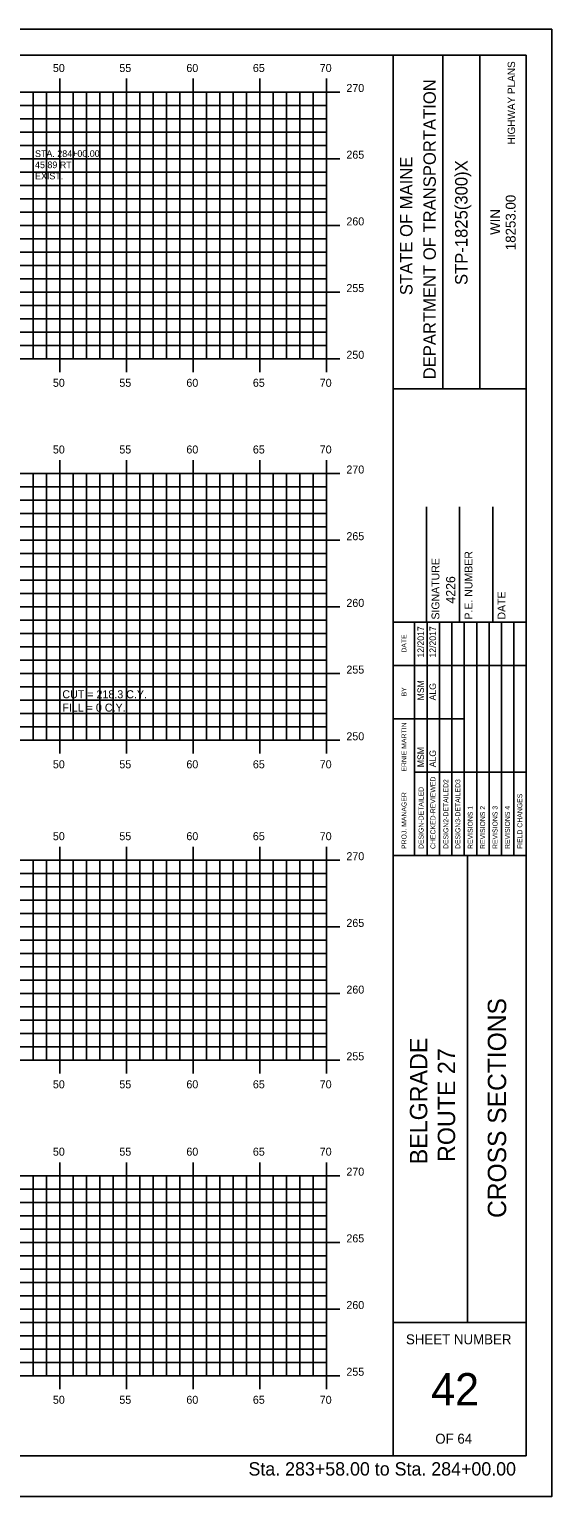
# Model space of a CAD drawing. Extents: x 856235 to 856405, y 366268 to 366378.
# Drawn here: x 856365.5 to 856404.7, y 366268.2 to 366378.2 of the extents above; entities that cross this region are included whole.
import ezdxf

# ---------------------------------------------------------------- set-up
doc = ezdxf.new("R2010")
doc.units = 0
for name, color, linetype in [('ANNOTATION', 7, 'Continuous'), ('BORDER', 7, 'Continuous'), ('D_Text_Monospaced', 7, 'Continuous'), ('H_V ANNOTATION', 7, 'Continuous'), ('HIGHWAY_TITLE', 7, 'Continuous'), ('MAJOR', 7, 'Continuous'), ('MINOR', 7, 'Continuous'), ('PLOT BOUNDARY', 7, 'Continuous')]:
    doc.layers.add(name, color=color, linetype=linetype)

msp = doc.modelspace()

# ---------------------------------------------------------------- linework, layer by layer
at = {"layer": 'BORDER'}
for p, q in [((856402.78, 366376.24), (856242.78, 366376.24)), ((856392.78, 366271.24), (856392.78, 366376.24)), ((856396.51, 366351.23), (856396.51, 366376.23)), ((856399.3, 366351.23), (856399.3, 366376.23)), ((856402.78, 366271.24), (856402.78, 366376.24)), ((856392.78, 366351.23), (856402.78, 366351.23)), ((856395.28, 366333.74), (856395.28, 366342.39)), ((856397.78, 366333.74), (856397.78, 366342.39)), ((856400.28, 366333.74), (856400.28, 366342.39)), ((856392.78, 366333.74), (856402.78, 366333.74)), ((856392.78, 366316.24), (856402.78, 366316.24)), ((856398.37, 366281.24), (856398.37, 366316.24)), ((856392.78, 366281.24), (856402.78, 366281.24)), ((856242.78, 366271.24), (856402.78, 366271.24))]:
    msp.add_line(p, q, dxfattribs=at)
for points in [[(856394.4, 366330.49), (856394.4, 366333.74)], [(856394.4, 366316.24), (856394.4, 366333.03)], [(856395.33, 366316.24), (856395.33, 366333.74)], [(856396.26, 366333.74), (856396.26, 366316.24)], [(856397.19, 366316.24), (856397.19, 366333.74)], [(856398.12, 366316.24), (856398.12, 366333.74)], [(856399.06, 366316.24), (856399.06, 366333.74)], [(856399.99, 366316.24), (856399.99, 366333.74)], [(856400.92, 366316.24), (856400.92, 366333.74)], [(856401.85, 366316.24), (856401.85, 366333.74)], [(856392.78, 366330.49), (856402.78, 366330.49)], [(856392.78, 366326.49), (856394.4, 366326.49)], [(856394.4, 366326.49), (856398.12, 366326.49)], [(856394.4, 366322.49), (856402.78, 366322.49)]]:
    msp.add_lwpolyline(points, dxfattribs=at)
at = {"layer": 'MAJOR'}
for p, q in [((856367.78, 366374.48), (856367.78, 366373.48)), ((856372.78, 366374.48), (856372.78, 366373.48)), ((856377.78, 366374.48), (856377.78, 366373.48)), ((856382.78, 366374.48), (856382.78, 366373.48)), ((856387.78, 366374.48), (856387.78, 366373.48)), ((856247.78, 366373.48), (856387.78, 366373.48)), ((856247.78, 366373.48), (856387.78, 366373.48)), ((856367.78, 366353.48), (856367.78, 366373.48)), ((856372.78, 366353.48), (856372.78, 366373.48)), ((856377.78, 366353.48), (856377.78, 366373.48)), ((856382.78, 366353.48), (856382.78, 366373.48)), ((856388.78, 366373.48), (856386.78, 366373.48)), ((856387.78, 366353.48), (856387.78, 366373.48)), ((856387.78, 366353.48), (856387.78, 366373.48)), ((856247.78, 366368.48), (856387.78, 366368.48)), ((856388.78, 366368.48), (856386.78, 366368.48)), ((856247.78, 366363.48), (856387.78, 366363.48)), ((856388.78, 366363.48), (856386.78, 366363.48)), ((856247.78, 366358.48), (856387.78, 366358.48)), ((856388.78, 366358.48), (856386.78, 366358.48)), ((856247.78, 366353.48), (856387.78, 366353.48)), ((856247.78, 366353.48), (856387.78, 366353.48)), ((856367.78, 366352.48), (856367.78, 366353.48)), ((856372.78, 366352.48), (856372.78, 366353.48)), ((856377.78, 366352.48), (856377.78, 366353.48)), ((856382.78, 366352.48), (856382.78, 366353.48)), ((856388.78, 366353.48), (856386.78, 366353.48)), ((856387.78, 366352.48), (856387.78, 366353.48)), ((856367.78, 366345.89), (856367.78, 366344.88)), ((856372.78, 366345.89), (856372.78, 366344.88)), ((856377.78, 366345.89), (856377.78, 366344.88)), ((856382.78, 366345.89), (856382.78, 366344.88)), ((856387.78, 366345.89), (856387.78, 366344.88)), ((856247.78, 366344.88), (856387.78, 366344.88)), ((856247.78, 366344.88), (856387.78, 366344.88)), ((856367.78, 366324.88), (856367.78, 366344.88)), ((856372.78, 366324.88), (856372.78, 366344.88)), ((856377.78, 366324.88), (856377.78, 366344.88)), ((856382.78, 366324.88), (856382.78, 366344.88)), ((856388.78, 366344.88), (856386.78, 366344.88)), ((856387.78, 366324.88), (856387.78, 366344.88)), ((856387.78, 366324.88), (856387.78, 366344.88)), ((856247.78, 366339.88), (856387.78, 366339.88)), ((856388.78, 366339.88), (856386.78, 366339.88)), ((856247.78, 366334.88), (856387.78, 366334.88)), ((856388.78, 366334.88), (856386.78, 366334.88)), ((856247.78, 366329.88), (856387.78, 366329.88)), ((856388.78, 366329.88), (856386.78, 366329.88)), ((856247.78, 366324.88), (856387.78, 366324.88)), ((856247.78, 366324.88), (856387.78, 366324.88)), ((856367.78, 366323.88), (856367.78, 366324.88)), ((856372.78, 366323.88), (856372.78, 366324.88)), ((856377.78, 366323.88), (856377.78, 366324.88)), ((856382.78, 366323.88), (856382.78, 366324.88)), ((856388.78, 366324.88), (856386.78, 366324.88)), ((856387.78, 366323.88), (856387.78, 366324.88)), ((856367.78, 366316.89), (856367.78, 366315.89)), ((856372.78, 366316.89), (856372.78, 366315.89)), ((856377.78, 366316.89), (856377.78, 366315.89)), ((856382.78, 366316.89), (856382.78, 366315.89)), ((856387.78, 366316.89), (856387.78, 366315.89)), ((856247.78, 366315.89), (856387.78, 366315.89)), ((856247.78, 366315.89), (856387.78, 366315.89)), ((856367.78, 366300.89), (856367.78, 366315.89)), ((856372.78, 366300.89), (856372.78, 366315.89)), ((856377.78, 366300.89), (856377.78, 366315.89)), ((856382.78, 366300.89), (856382.78, 366315.89)), ((856388.78, 366315.89), (856386.78, 366315.89)), ((856387.78, 366300.89), (856387.78, 366315.89)), ((856387.78, 366300.89), (856387.78, 366315.89)), ((856247.78, 366310.89), (856387.78, 366310.89)), ((856388.78, 366310.89), (856386.78, 366310.89)), ((856247.78, 366305.89), (856387.78, 366305.89)), ((856388.78, 366305.89), (856386.78, 366305.89)), ((856247.78, 366300.89), (856387.78, 366300.89)), ((856247.78, 366300.89), (856387.78, 366300.89)), ((856367.78, 366299.89), (856367.78, 366300.89)), ((856372.78, 366299.89), (856372.78, 366300.89)), ((856377.78, 366299.89), (856377.78, 366300.89)), ((856382.78, 366299.89), (856382.78, 366300.89)), ((856388.78, 366300.89), (856386.78, 366300.89)), ((856387.78, 366299.89), (856387.78, 366300.89)), ((856367.78, 366293.24), (856367.78, 366292.24)), ((856372.78, 366293.24), (856372.78, 366292.24)), ((856377.78, 366293.24), (856377.78, 366292.24)), ((856382.78, 366293.24), (856382.78, 366292.24)), ((856387.78, 366293.24), (856387.78, 366292.24)), ((856247.78, 366292.24), (856387.78, 366292.24)), ((856247.78, 366292.24), (856387.78, 366292.24)), ((856367.78, 366277.24), (856367.78, 366292.24)), ((856372.78, 366277.24), (856372.78, 366292.24)), ((856377.78, 366277.24), (856377.78, 366292.24)), ((856382.78, 366277.24), (856382.78, 366292.24)), ((856388.78, 366292.24), (856386.78, 366292.24)), ((856387.78, 366277.24), (856387.78, 366292.24)), ((856387.78, 366277.24), (856387.78, 366292.24)), ((856247.78, 366287.24), (856387.78, 366287.24)), ((856388.78, 366287.24), (856386.78, 366287.24)), ((856247.78, 366282.24), (856387.78, 366282.24)), ((856388.78, 366282.24), (856386.78, 366282.24)), ((856247.78, 366277.24), (856387.78, 366277.24)), ((856247.78, 366277.24), (856387.78, 366277.24)), ((856367.78, 366276.23), (856367.78, 366277.24)), ((856372.78, 366276.23), (856372.78, 366277.24)), ((856377.78, 366276.23), (856377.78, 366277.24)), ((856382.78, 366276.23), (856382.78, 366277.24)), ((856388.78, 366277.24), (856386.78, 366277.24)), ((856387.78, 366276.23), (856387.78, 366277.24))]:
    msp.add_line(p, q, dxfattribs=at)
at = {"layer": 'MINOR'}
for p, q in [((856365.78, 366353.48), (856365.78, 366373.48)), ((856366.78, 366353.48), (856366.78, 366373.48)), ((856368.78, 366353.48), (856368.78, 366373.48)), ((856369.78, 366353.48), (856369.78, 366373.48)), ((856370.78, 366353.48), (856370.78, 366373.48)), ((856371.78, 366353.48), (856371.78, 366373.48)), ((856373.78, 366353.48), (856373.78, 366373.48)), ((856374.78, 366353.48), (856374.78, 366373.48)), ((856375.78, 366353.48), (856375.78, 366373.48)), ((856376.78, 366353.48), (856376.78, 366373.48)), ((856378.78, 366353.48), (856378.78, 366373.48)), ((856379.78, 366353.48), (856379.78, 366373.48)), ((856380.78, 366353.48), (856380.78, 366373.48)), ((856381.78, 366353.48), (856381.78, 366373.48)), ((856383.78, 366353.48), (856383.78, 366373.48)), ((856384.78, 366353.48), (856384.78, 366373.48)), ((856385.78, 366353.48), (856385.78, 366373.48)), ((856386.78, 366353.48), (856386.78, 366373.48)), ((856247.78, 366372.48), (856387.78, 366372.48)), ((856387.78, 366372.48), (856386.78, 366372.48)), ((856247.78, 366371.48), (856387.78, 366371.48)), ((856247.78, 366370.48), (856387.78, 366370.48)), ((856387.78, 366371.48), (856386.78, 366371.48)), ((856387.78, 366370.48), (856386.78, 366370.48)), ((856247.78, 366369.48), (856387.78, 366369.48)), ((856387.78, 366369.48), (856386.78, 366369.48)), ((856247.78, 366367.48), (856387.78, 366367.48)), ((856387.78, 366367.48), (856386.78, 366367.48)), ((856247.78, 366366.48), (856387.78, 366366.48)), ((856387.78, 366366.48), (856386.78, 366366.48)), ((856247.78, 366365.48), (856387.78, 366365.48)), ((856387.78, 366365.48), (856386.78, 366365.48)), ((856247.78, 366364.48), (856387.78, 366364.48)), ((856387.78, 366364.48), (856386.78, 366364.48)), ((856247.78, 366362.48), (856387.78, 366362.48)), ((856387.78, 366362.48), (856386.78, 366362.48)), ((856247.78, 366361.48), (856387.78, 366361.48)), ((856387.78, 366361.48), (856386.78, 366361.48)), ((856247.78, 366360.48), (856387.78, 366360.48)), ((856247.78, 366359.48), (856387.78, 366359.48)), ((856387.78, 366360.48), (856386.78, 366360.48)), ((856387.78, 366359.48), (856386.78, 366359.48)), ((856247.78, 366357.48), (856387.78, 366357.48)), ((856387.78, 366357.48), (856386.78, 366357.48)), ((856247.78, 366356.48), (856387.78, 366356.48)), ((856387.78, 366356.48), (856386.78, 366356.48)), ((856247.78, 366355.48), (856387.78, 366355.48)), ((856387.78, 366355.48), (856386.78, 366355.48)), ((856247.78, 366354.48), (856387.78, 366354.48)), ((856387.78, 366354.48), (856386.78, 366354.48)), ((856365.78, 366324.88), (856365.78, 366344.88)), ((856366.78, 366324.88), (856366.78, 366344.88)), ((856368.78, 366324.88), (856368.78, 366344.88)), ((856369.78, 366324.88), (856369.78, 366344.88)), ((856370.78, 366324.88), (856370.78, 366344.88)), ((856371.78, 366324.88), (856371.78, 366344.88)), ((856373.78, 366324.88), (856373.78, 366344.88)), ((856374.78, 366324.88), (856374.78, 366344.88)), ((856375.78, 366324.88), (856375.78, 366344.88)), ((856376.78, 366324.88), (856376.78, 366344.88)), ((856378.78, 366324.88), (856378.78, 366344.88)), ((856379.78, 366324.88), (856379.78, 366344.88)), ((856380.78, 366324.88), (856380.78, 366344.88)), ((856381.78, 366324.88), (856381.78, 366344.88)), ((856383.78, 366324.88), (856383.78, 366344.88)), ((856384.78, 366324.88), (856384.78, 366344.88)), ((856385.78, 366324.88), (856385.78, 366344.88)), ((856386.78, 366324.88), (856386.78, 366344.88)), ((856247.78, 366343.88), (856387.78, 366343.88)), ((856387.78, 366343.88), (856386.78, 366343.88)), ((856247.78, 366342.88), (856387.78, 366342.88)), ((856247.78, 366341.88), (856387.78, 366341.88)), ((856387.78, 366342.88), (856386.78, 366342.88)), ((856387.78, 366341.88), (856386.78, 366341.88)), ((856247.78, 366340.88), (856387.78, 366340.88)), ((856387.78, 366340.88), (856386.78, 366340.88)), ((856247.78, 366338.88), (856387.78, 366338.88)), ((856387.78, 366338.88), (856386.78, 366338.88)), ((856247.78, 366337.88), (856387.78, 366337.88)), ((856387.78, 366337.88), (856386.78, 366337.88)), ((856247.78, 366336.88), (856387.78, 366336.88)), ((856387.78, 366336.88), (856386.78, 366336.88)), ((856247.78, 366335.88), (856387.78, 366335.88)), ((856387.78, 366335.88), (856386.78, 366335.88)), ((856247.78, 366333.88), (856387.78, 366333.88)), ((856387.78, 366333.88), (856386.78, 366333.88)), ((856247.78, 366332.88), (856387.78, 366332.88)), ((856387.78, 366332.88), (856386.78, 366332.88)), ((856247.78, 366331.88), (856387.78, 366331.88)), ((856247.78, 366330.88), (856387.78, 366330.88)), ((856387.78, 366331.88), (856386.78, 366331.88)), ((856387.78, 366330.88), (856386.78, 366330.88)), ((856247.78, 366328.88), (856387.78, 366328.88)), ((856387.78, 366328.88), (856386.78, 366328.88)), ((856247.78, 366327.88), (856387.78, 366327.88)), ((856387.78, 366327.88), (856386.78, 366327.88)), ((856247.78, 366326.88), (856387.78, 366326.88)), ((856387.78, 366326.88), (856386.78, 366326.88)), ((856247.78, 366325.88), (856387.78, 366325.88)), ((856387.78, 366325.88), (856386.78, 366325.88)), ((856365.78, 366300.89), (856365.78, 366315.89)), ((856366.78, 366300.89), (856366.78, 366315.89)), ((856368.78, 366300.89), (856368.78, 366315.89)), ((856369.78, 366300.89), (856369.78, 366315.89)), ((856370.78, 366300.89), (856370.78, 366315.89)), ((856371.78, 366300.89), (856371.78, 366315.89)), ((856373.78, 366300.89), (856373.78, 366315.89)), ((856374.78, 366300.89), (856374.78, 366315.89)), ((856375.78, 366300.89), (856375.78, 366315.89)), ((856376.78, 366300.89), (856376.78, 366315.89)), ((856378.78, 366300.89), (856378.78, 366315.89)), ((856379.78, 366300.89), (856379.78, 366315.89)), ((856380.78, 366300.89), (856380.78, 366315.89)), ((856381.78, 366300.89), (856381.78, 366315.89)), ((856383.78, 366300.89), (856383.78, 366315.89)), ((856384.78, 366300.89), (856384.78, 366315.89)), ((856385.78, 366300.89), (856385.78, 366315.89)), ((856386.78, 366300.89), (856386.78, 366315.89)), ((856247.78, 366314.89), (856387.78, 366314.89)), ((856387.78, 366314.89), (856386.78, 366314.89)), ((856247.78, 366313.89), (856387.78, 366313.89)), ((856387.78, 366313.89), (856386.78, 366313.89)), ((856247.78, 366312.89), (856387.78, 366312.89)), ((856387.78, 366312.89), (856386.78, 366312.89)), ((856247.78, 366311.89), (856387.78, 366311.89)), ((856387.78, 366311.89), (856386.78, 366311.89)), ((856247.78, 366309.89), (856387.78, 366309.89)), ((856247.78, 366308.89), (856387.78, 366308.89)), ((856387.78, 366309.89), (856386.78, 366309.89)), ((856387.78, 366308.89), (856386.78, 366308.89)), ((856247.78, 366307.89), (856387.78, 366307.89)), ((856387.78, 366307.89), (856386.78, 366307.89)), ((856247.78, 366306.89), (856387.78, 366306.89)), ((856387.78, 366306.89), (856386.78, 366306.89)), ((856247.78, 366304.89), (856387.78, 366304.89)), ((856387.78, 366304.89), (856386.78, 366304.89)), ((856247.78, 366303.89), (856387.78, 366303.89)), ((856387.78, 366303.89), (856386.78, 366303.89)), ((856247.78, 366302.89), (856387.78, 366302.89)), ((856387.78, 366302.89), (856386.78, 366302.89)), ((856247.78, 366301.89), (856387.78, 366301.89)), ((856387.78, 366301.89), (856386.78, 366301.89)), ((856247.78, 366291.24), (856387.78, 366291.24)), ((856365.78, 366277.24), (856365.78, 366292.24)), ((856366.78, 366277.24), (856366.78, 366292.24)), ((856368.78, 366277.24), (856368.78, 366292.24)), ((856369.78, 366277.24), (856369.78, 366292.24)), ((856370.78, 366277.24), (856370.78, 366292.24)), ((856371.78, 366277.24), (856371.78, 366292.24)), ((856373.78, 366277.24), (856373.78, 366292.24)), ((856374.78, 366277.24), (856374.78, 366292.24)), ((856375.78, 366277.24), (856375.78, 366292.24)), ((856376.78, 366277.24), (856376.78, 366292.24)), ((856378.78, 366277.24), (856378.78, 366292.24)), ((856379.78, 366277.24), (856379.78, 366292.24)), ((856380.78, 366277.24), (856380.78, 366292.24)), ((856381.78, 366277.24), (856381.78, 366292.24)), ((856383.78, 366277.24), (856383.78, 366292.24)), ((856384.78, 366277.24), (856384.78, 366292.24)), ((856385.78, 366277.24), (856385.78, 366292.24)), ((856386.78, 366277.24), (856386.78, 366292.24)), ((856387.78, 366291.24), (856386.78, 366291.24)), ((856247.78, 366290.24), (856387.78, 366290.24)), ((856387.78, 366290.24), (856386.78, 366290.24)), ((856247.78, 366289.24), (856387.78, 366289.24)), ((856387.78, 366289.24), (856386.78, 366289.24)), ((856247.78, 366288.24), (856387.78, 366288.24)), ((856387.78, 366288.24), (856386.78, 366288.24)), ((856247.78, 366286.24), (856387.78, 366286.24)), ((856387.78, 366286.24), (856386.78, 366286.24)), ((856247.78, 366285.24), (856387.78, 366285.24)), ((856387.78, 366285.24), (856386.78, 366285.24)), ((856247.78, 366284.24), (856387.78, 366284.24)), ((856387.78, 366284.24), (856386.78, 366284.24)), ((856247.78, 366283.24), (856387.78, 366283.24)), ((856387.78, 366283.24), (856386.78, 366283.24)), ((856247.78, 366281.24), (856387.78, 366281.24)), ((856247.78, 366280.24), (856387.78, 366280.24)), ((856387.78, 366281.24), (856386.78, 366281.24)), ((856387.78, 366280.24), (856386.78, 366280.24)), ((856247.78, 366279.24), (856387.78, 366279.24)), ((856387.78, 366279.24), (856386.78, 366279.24)), ((856247.78, 366278.24), (856387.78, 366278.24)), ((856387.78, 366278.24), (856386.78, 366278.24))]:
    msp.add_line(p, q, dxfattribs=at)
at = {"layer": 'PLOT BOUNDARY'}
msp.add_lwpolyline([(856234.69, 366268.18), (856404.69, 366268.18), (856404.69, 366378.18), (856234.69, 366378.18)], close=True, dxfattribs=at)

# ---------------------------------------------------------------- texts
at = {"layer": 'ANNOTATION'}
msp.add_text('4226', height=0.69, rotation=90, dxfattribs=at).set_placement((856397.45, 366335.13))
for s, p in [('CUT = 218.3 C.Y.', (856367.96, 366328.03)), ('FILL = 0 C.Y.', (856367.96, 366327.03))]:
    msp.add_text(s, height=0.6, dxfattribs=at).set_placement(p)
at = {"layer": 'BORDER'}
for s, height, rotation, p in [('DEPARTMENT OF TRANSPORTATION', 0.9318, 90, (856395.99, 366351.94)), ('STATE OF MAINE', 0.9318, 90, (856394.24, 366358.25)), ('STP-1825(300)X', 0.9318, 90, (856398.37, 366359.01)), ('18253.00', 0.745, 90, (856401.98, 366361.62)), ('WIN', 0.745, 90, (856400.82, 366362.77)), ('SIGNATURE', 0.591, 90, (856396.26, 366333.93)), ('P.E. NUMBER', 0.5906, 90, (856398.74, 366333.93)), ('DATE', 0.591, 90, (856401.22, 366333.93)), ('12/2017', 0.485, 90, (856395.1, 366331.08)), ('12/2017', 0.485, 90, (856396, 366331.08)), ('DATE', 0.371, 90, (856393.79, 366331.45)), ('BY', 0.371, 90, (856393.79, 366328.17)), ('MSM', 0.485, 90, (856395.1, 366327.87)), ('ALG', 0.485, 90, (856396, 366327.87)), ('ERNIE MARTIN', 0.3727, 90, (856393.79, 366322.53)), ('MSM', 0.485, 90, (856395.1, 366322.86)), ('ALG', 0.485, 90, (856396, 366322.86)), ('DESIGN-DETAILED', 0.3727, 90, (856395.07, 366316.73)), ('CHECKED-REVIEWED', 0.3727, 90, (856395.96, 366316.73)), ('DESIGN2-DETAILED2', 0.3727, 90, (856396.93, 366316.73)), ('DESIGN3-DETAILED3', 0.3727, 90, (856397.83, 366316.73)), ('PROJ. MANAGER', 0.3727, 90, (856393.79, 366316.73)), ('REVISIONS 1', 0.3727, 90, (856398.76, 366316.73)), ('REVISIONS 2', 0.3727, 90, (856399.69, 366316.73)), ('REVISIONS 3', 0.3727, 90, (856400.62, 366316.73)), ('REVISIONS 4', 0.3727, 90, (856401.55, 366316.73)), ('FIELD CHANGES', 0.3727, 90, (856402.48, 366316.73)), ('CROSS SECTIONS', 1.3779, 90, (856401.27, 366289.07)), ('SHEET NUMBER', 0.7453, 360, (856393.75, 366279.6)), ('42', 2.419, 360, (856395.64, 366275.02)), ('OF 64', 0.745, 360, (856395.95, 366272.15))]:
    msp.add_text(s, height=height, rotation=rotation, dxfattribs=at).set_placement(p)
at = {"layer": 'D_Text_Monospaced'}
for s, p in [('45.89 RT.', (856365.91, 366367.77)), ('STA. 284+00.00', (856365.91, 366368.61)), ('EXIST. ', (856365.91, 366366.93))]:
    msp.add_text(s, height=0.5, dxfattribs=at).set_placement(p)
at = {"layer": 'H_V ANNOTATION'}
for s, height, p in [('50', 0.6, (856367.25, 366374.98)), ('55', 0.6, (856372.24, 366374.98)), ('60', 0.6, (856377.27, 366374.98)), ('65', 0.6, (856382.26, 366374.98)), ('70', 0.6, (856387.28, 366374.98)), ('270', 0.6, (856389.28, 366373.48)), ('265', 0.6, (856389.28, 366368.48)), ('260', 0.6, (856389.28, 366363.48)), ('255', 0.6, (856389.28, 366358.48)), ('250', 0.6, (856389.28, 366353.48)), ('50', 0.6, (856367.25, 366351.38)), ('55', 0.6, (856372.24, 366351.38)), ('60', 0.6, (856377.27, 366351.38)), ('65', 0.6, (856382.26, 366351.38)), ('70', 0.6, (856387.28, 366351.38)), ('50', 0.6, (856367.25, 366346.38)), ('55', 0.6, (856372.24, 366346.38)), ('60', 0.6, (856377.27, 366346.38)), ('65', 0.6, (856382.26, 366346.38)), ('70', 0.6, (856387.28, 366346.38)), ('270', 0.6, (856389.28, 366344.88)), ('265', 0.6, (856389.28, 366339.88)), ('260', 0.6, (856389.28, 366334.88)), ('255', 0.6, (856389.28, 366329.88)), ('250', 0.6, (856389.28, 366324.88)), ('50', 0.6, (856367.25, 366322.78)), ('55', 0.6, (856372.24, 366322.78)), ('60', 0.6, (856377.27, 366322.78)), ('65', 0.6, (856382.26, 366322.78)), ('70', 0.6, (856387.28, 366322.78)), ('50', 0.6, (856367.25, 366317.39)), ('55', 0.6, (856372.24, 366317.39)), ('60', 0.6, (856377.27, 366317.39)), ('65', 0.6, (856382.26, 366317.39)), ('70', 0.6, (856387.28, 366317.39)), ('270', 0.6, (856389.28, 366315.89)), ('265', 0.6, (856389.28, 366310.89)), ('260', 0.6, (856389.28, 366305.89)), ('255', 0.6, (856389.28, 366300.89)), ('50', 0.6, (856367.25, 366298.79)), ('55', 0.6, (856372.24, 366298.79)), ('60', 0.6, (856377.27, 366298.79)), ('65', 0.6, (856382.26, 366298.79)), ('70', 0.6, (856387.28, 366298.79)), ('50', 0.6, (856367.25, 366293.74)), ('55', 0.6, (856372.24, 366293.74)), ('60', 0.6, (856377.27, 366293.74)), ('65', 0.6, (856382.26, 366293.74)), ('70', 0.6, (856387.28, 366293.74)), ('270', 0.6, (856389.28, 366292.24)), ('265', 0.6, (856389.28, 366287.24)), ('260', 0.6, (856389.28, 366282.24)), ('255', 0.6, (856389.28, 366277.24)), ('50', 0.6, (856367.25, 366275.14)), ('55', 0.6, (856372.24, 366275.14)), ('60', 0.6, (856377.27, 366275.14)), ('65', 0.6, (856382.26, 366275.14)), ('70', 0.6, (856387.28, 366275.14)), ('Sta. 283+58.00 to Sta. 284+00.00', 1.0002, (856381.93, 366269.76))]:
    msp.add_text(s, height=height, dxfattribs=at).set_placement(p)
at = {"layer": 'HIGHWAY_TITLE'}
for s, height, p in [('HIGHWAY PLANS', 0.559, (856401.94, 366369.55)), ('BELGRADE', 1.304, (856395.35, 366293.09)), ('ROUTE 27', 1.304, (856397.44, 366293.27))]:
    msp.add_text(s, height=height, rotation=90, dxfattribs=at).set_placement(p)

doc.saveas('drawing.dxf')
